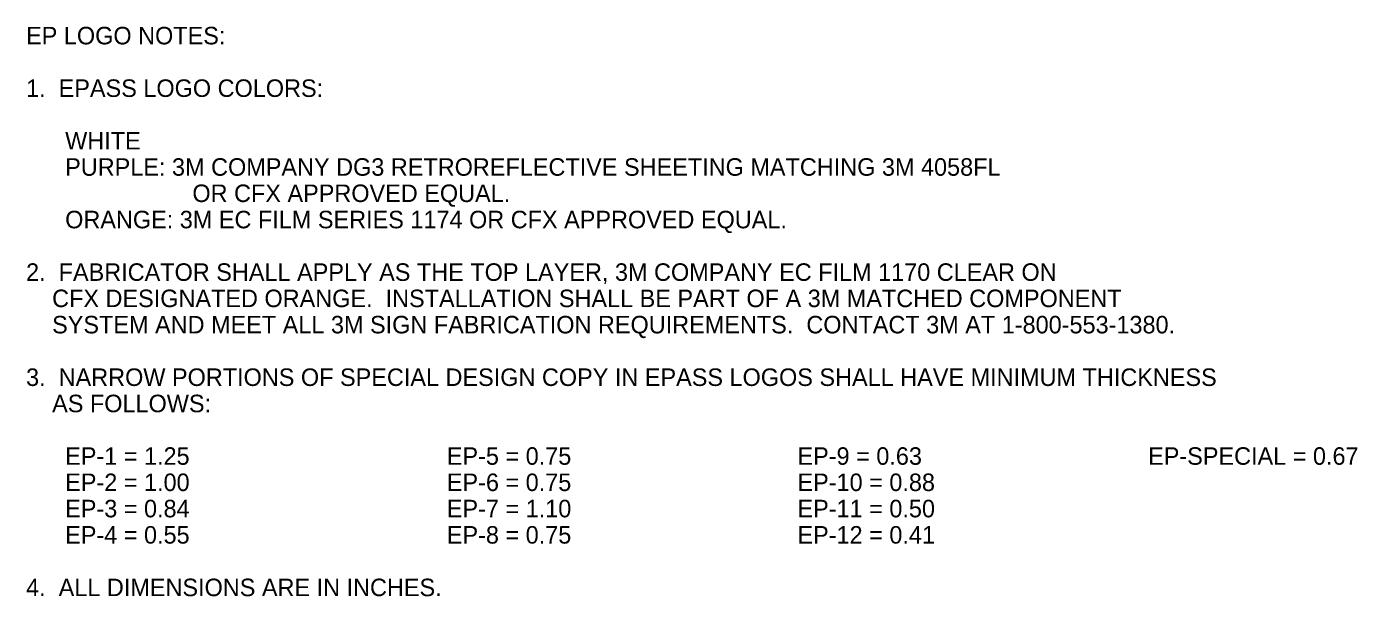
# Model space of a CAD drawing. Extents: x 10268197 to 10269179, y 2141503 to 2142677.
# Drawn here: x 10268751.8 to 10268805, y 2142099.1 to 2142121.9 of the extents above; entities that cross this region are included whole.
import ezdxf

# ---------------------------------------------------------------- set-up
doc = ezdxf.new("R2010")
doc.units = 0
doc.layers.add('TextNotes', color=7, linetype='Continuous')

msp = doc.modelspace()

# ---------------------------------------------------------------- texts
at = {"layer": 'TextNotes'}
for s, p in [('EP LOGO NOTES:', (10268751.799, 2142121.167)), ('1.  EPASS LOGO COLORS:', (10268751.799, 2142119.067)), ('      WHITE', (10268751.799, 2142116.967)), ('      PURPLE: 3M COMPANY DG3 RETROREFLECTIVE SHEETING MATCHING 3M 4058FL ', (10268751.799, 2142115.917)), ('    OR CFX APPROVED EQUAL.', (10268757.399, 2142114.867)), ('      ORANGE: 3M EC FILM SERIES 1174 OR CFX APPROVED EQUAL.', (10268751.799, 2142113.817)), ('2.  FABRICATOR SHALL APPLY AS THE TOP LAYER, 3M COMPANY EC FILM 1170 CLEAR ON', (10268751.799, 2142111.717)), ('    CFX DESIGNATED ORANGE.  INSTALLATION SHALL BE PART OF A 3M MATCHED COMPONENT', (10268751.799, 2142110.667)), ('    SYSTEM AND MEET ALL 3M SIGN FABRICATION REQUIREMENTS.  CONTACT 3M AT 1-800-553-1380.', (10268751.799, 2142109.617)), ('3.  NARROW PORTIONS OF SPECIAL DESIGN COPY IN EPASS LOGOS SHALL HAVE MINIMUM THICKNESS', (10268751.799, 2142107.517)), ('    AS FOLLOWS:', (10268751.799, 2142106.467)), ('      EP-1 = 1.25', (10268751.799, 2142104.367)), ('EP-5 = 0.75', (10268768.599, 2142104.367)), ('EP-9 = 0.63', (10268782.599, 2142104.367)), ('EP-SPECIAL = 0.67', (10268796.599, 2142104.367)), ('      EP-2 = 1.00', (10268751.799, 2142103.317)), ('EP-6 = 0.75', (10268768.599, 2142103.317)), ('EP-10 = 0.88', (10268782.599, 2142103.317)), ('      EP-3 = 0.84', (10268751.799, 2142102.267)), ('EP-7 = 1.10', (10268768.599, 2142102.267)), ('EP-11 = 0.50', (10268782.599, 2142102.267)), ('      EP-4 = 0.55', (10268751.799, 2142101.217)), ('EP-8 = 0.75', (10268768.599, 2142101.217)), ('EP-12 = 0.41', (10268782.599, 2142101.217)), ('4.  ALL DIMENSIONS ARE IN INCHES.', (10268751.799, 2142099.117))]:
    msp.add_text(s, height=0.7, dxfattribs=at).set_placement(p)

doc.saveas('drawing.dxf')
